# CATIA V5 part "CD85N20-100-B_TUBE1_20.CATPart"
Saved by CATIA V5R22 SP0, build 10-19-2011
Part number: CD85N20-100-B_TUBE1_20
Revision: ANY
Definition: UNKNOWN
Nomenclature: CD85N20-100-B_TUBE1_20
Source: Unknown
Bounding box of the stored display mesh (mm): x -10.8 to 10.8, y -10.8 to 10.79, z -66 to 66
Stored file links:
  D:\CAO_PER_MODIF_2025\CAO_PER_pick&place_2024P\Sous_Ensemble_Flacon\Verin\CD85N20-100-B_TUBE1_20.CATPart
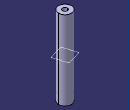
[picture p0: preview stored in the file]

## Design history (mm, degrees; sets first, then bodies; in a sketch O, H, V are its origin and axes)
Set1
  Plane1: type Offset, Offset 66, RefPlane DatumSurface1, reversed
  DatumSurface1
Body1 "CHAMBER" (main body)
  Solid1: solid without history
